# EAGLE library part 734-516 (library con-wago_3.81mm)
Serie 734, Federleiste mit geraden Einlötstiften / Series 734, Female connector with straight solder pins Polzahl / Pole No.: 16 Bemessungsspannung / Rated Voltage: 160 V Nennstrom / Nominal Current: 10 A Lötstiftlänge: / Solder Pin Length: 3.8 mm Farbe / Color: orange / orange Stand: 01.01.2012. Die jeweils aktuellen Daten zu diesem Artikel finden Sie in unserem Produktkatalog, den Sie unter www.wago.com einsehen können. As of: 01/01/2012. Please find the newest data for this article in our product catalogue, which can be viewed under www.wago.com.
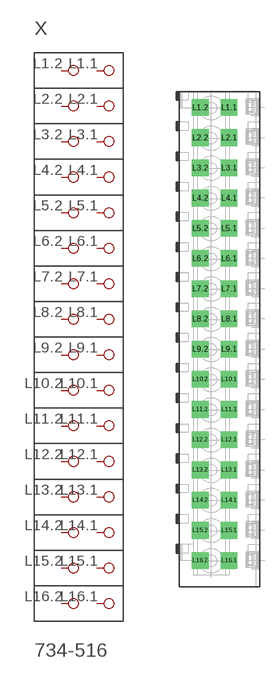
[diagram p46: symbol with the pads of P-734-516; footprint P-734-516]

Designator prefix X

## 734-516  [P-734-516]
L1.1  P1.1
L1.2  P1.2
L2.1  P2.1
L2.2  P2.2
L3.1  P3.1
L3.2  P3.2
L4.1  P4.1
L4.2  P4.2
L5.1  P5.1
L5.2  P5.2
L6.1  P6.1
L6.2  P6.2
L7.1  P7.1
L7.2  P7.2
L8.1  P8.1
L8.2  P8.2
L9.1  P9.1
L9.2  P9.2
L10.1  P10.1
L10.2  P10.2
L11.1  P11.1
L11.2  P11.2
L12.1  P12.1
L12.2  P12.2
L13.1  P13.1
L13.2  P13.2
L14.1  P14.1
L14.2  P14.2
L15.1  P15.1
L15.2  P15.2
L16.1  P16.1
L16.2  P16.2

## Footprint P-734-516 (pad centres in mm)
drill 1.4 square: L1.1 1.077,29.177; L1.2 -2.573,29.177; L2.1 1.077,25.367; L2.2 -2.573,25.367; L3.1 1.077,21.557; L3.2 -2.573,21.557; L4.1 1.077,17.747; L4.2 -2.573,17.747; L5.1 1.077,13.937; L5.2 -2.573,13.937; L6.1 1.077,10.127; L6.2 -2.573,10.127; L7.1 1.077,6.317; L7.2 -2.573,6.317; L8.1 1.077,2.507; L8.2 -2.573,2.507; L9.1 1.077,-1.303; L9.2 -2.573,-1.303; L10.1 1.077,-5.113; L10.2 -2.573,-5.113; L11.1 1.077,-8.923; L11.2 -2.573,-8.923; L12.1 1.077,-12.733; L12.2 -2.573,-12.733; L13.1 1.077,-16.543; L13.2 -2.573,-16.543; L14.1 1.077,-20.353; L14.2 -2.573,-20.353; L15.1 1.077,-24.163; L15.2 -2.573,-24.163; L16.1 1.077,-27.973; L16.2 -2.573,-27.973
